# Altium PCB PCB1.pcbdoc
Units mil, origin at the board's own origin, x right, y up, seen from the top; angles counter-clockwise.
Board outline 4705 x 4455 mil, 2 copper layers (Top Layer, Bottom Layer), stack 62.206 mil thick; 55 components, 35 nets, 221 pads, 60 vias.
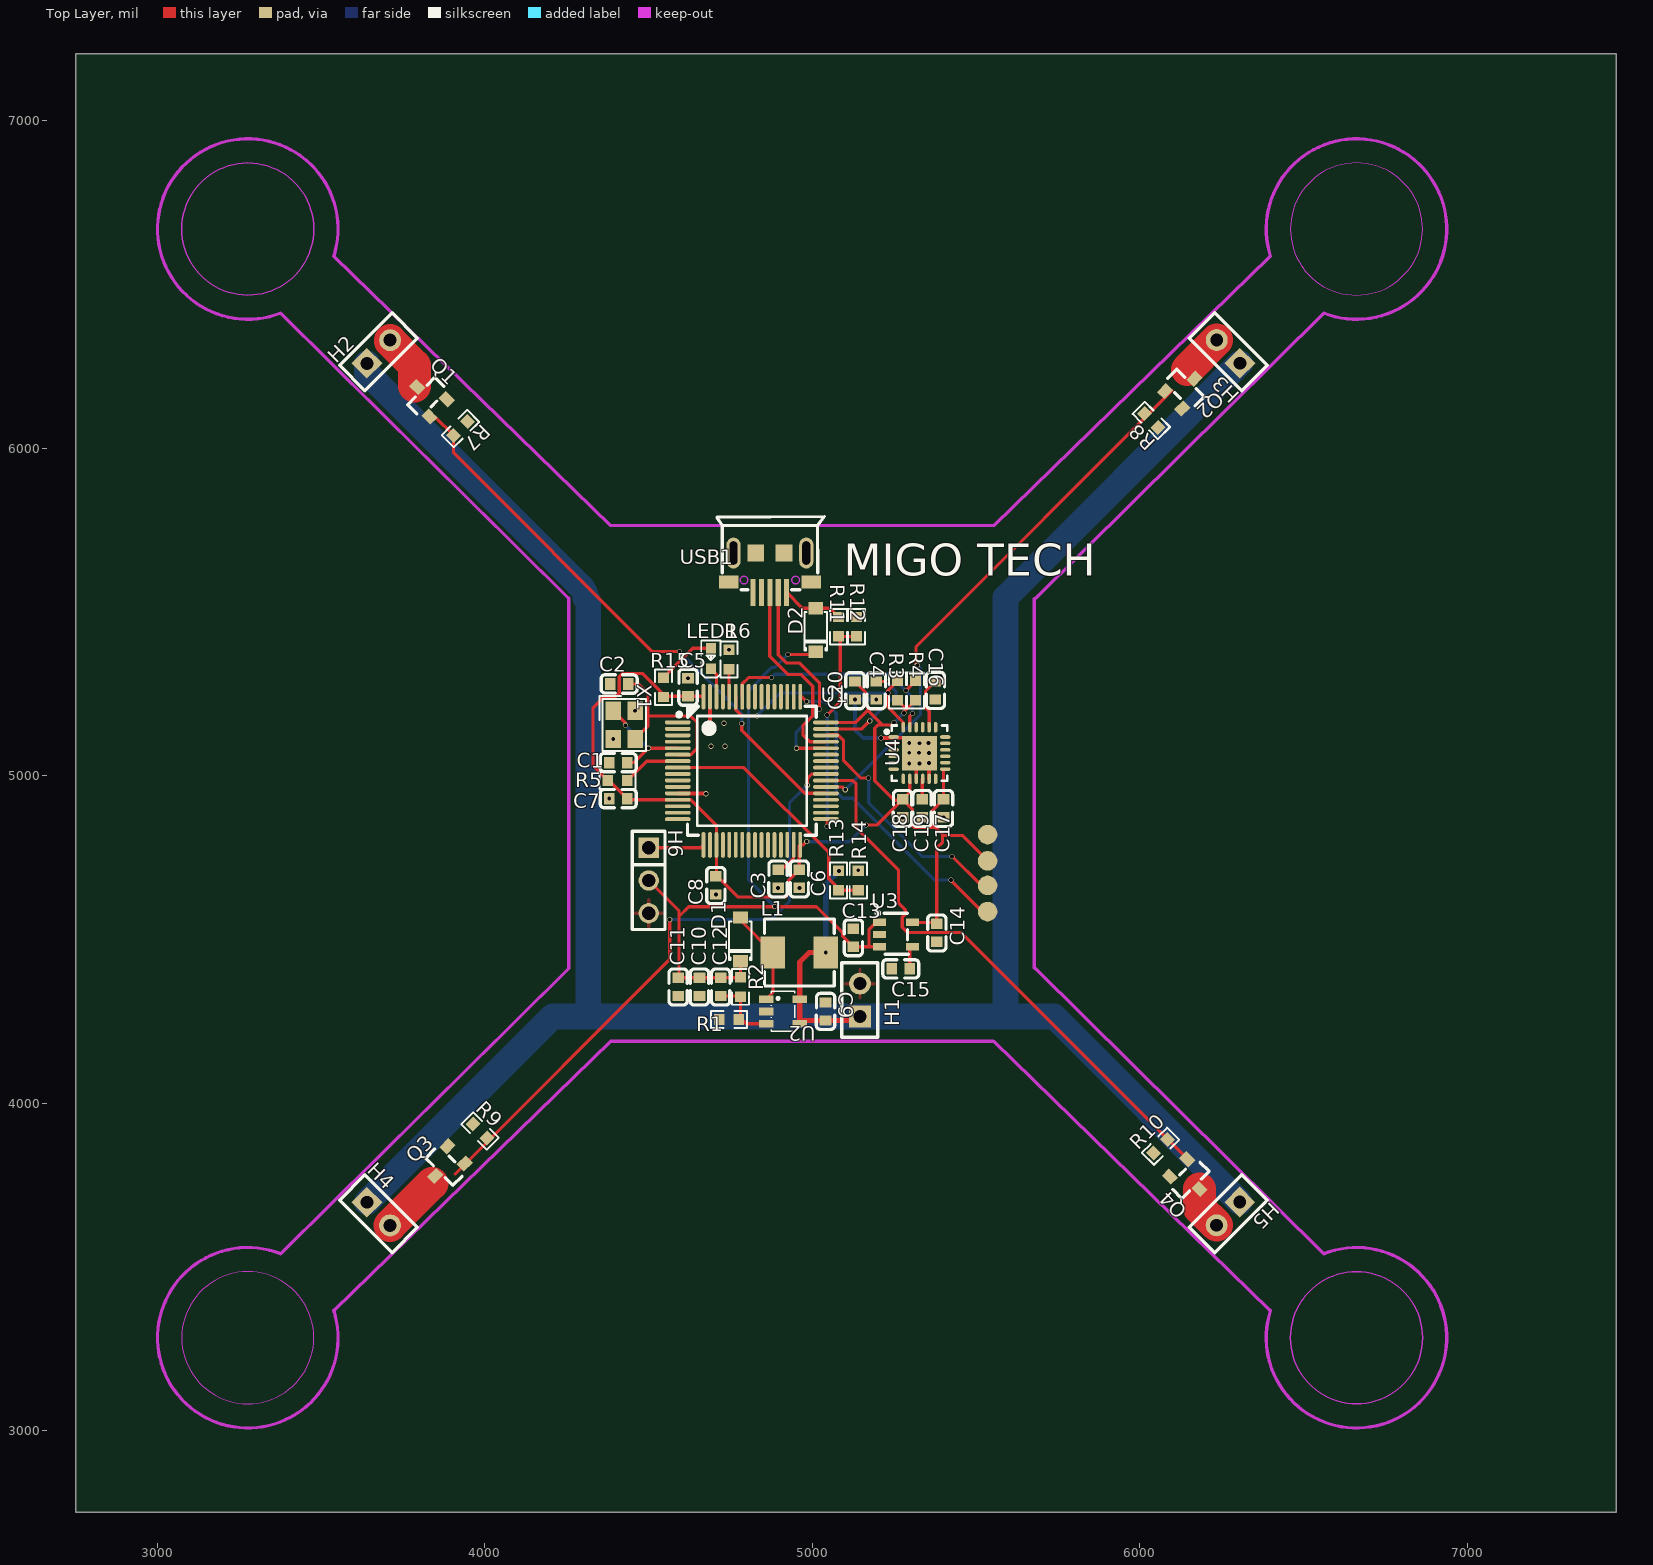
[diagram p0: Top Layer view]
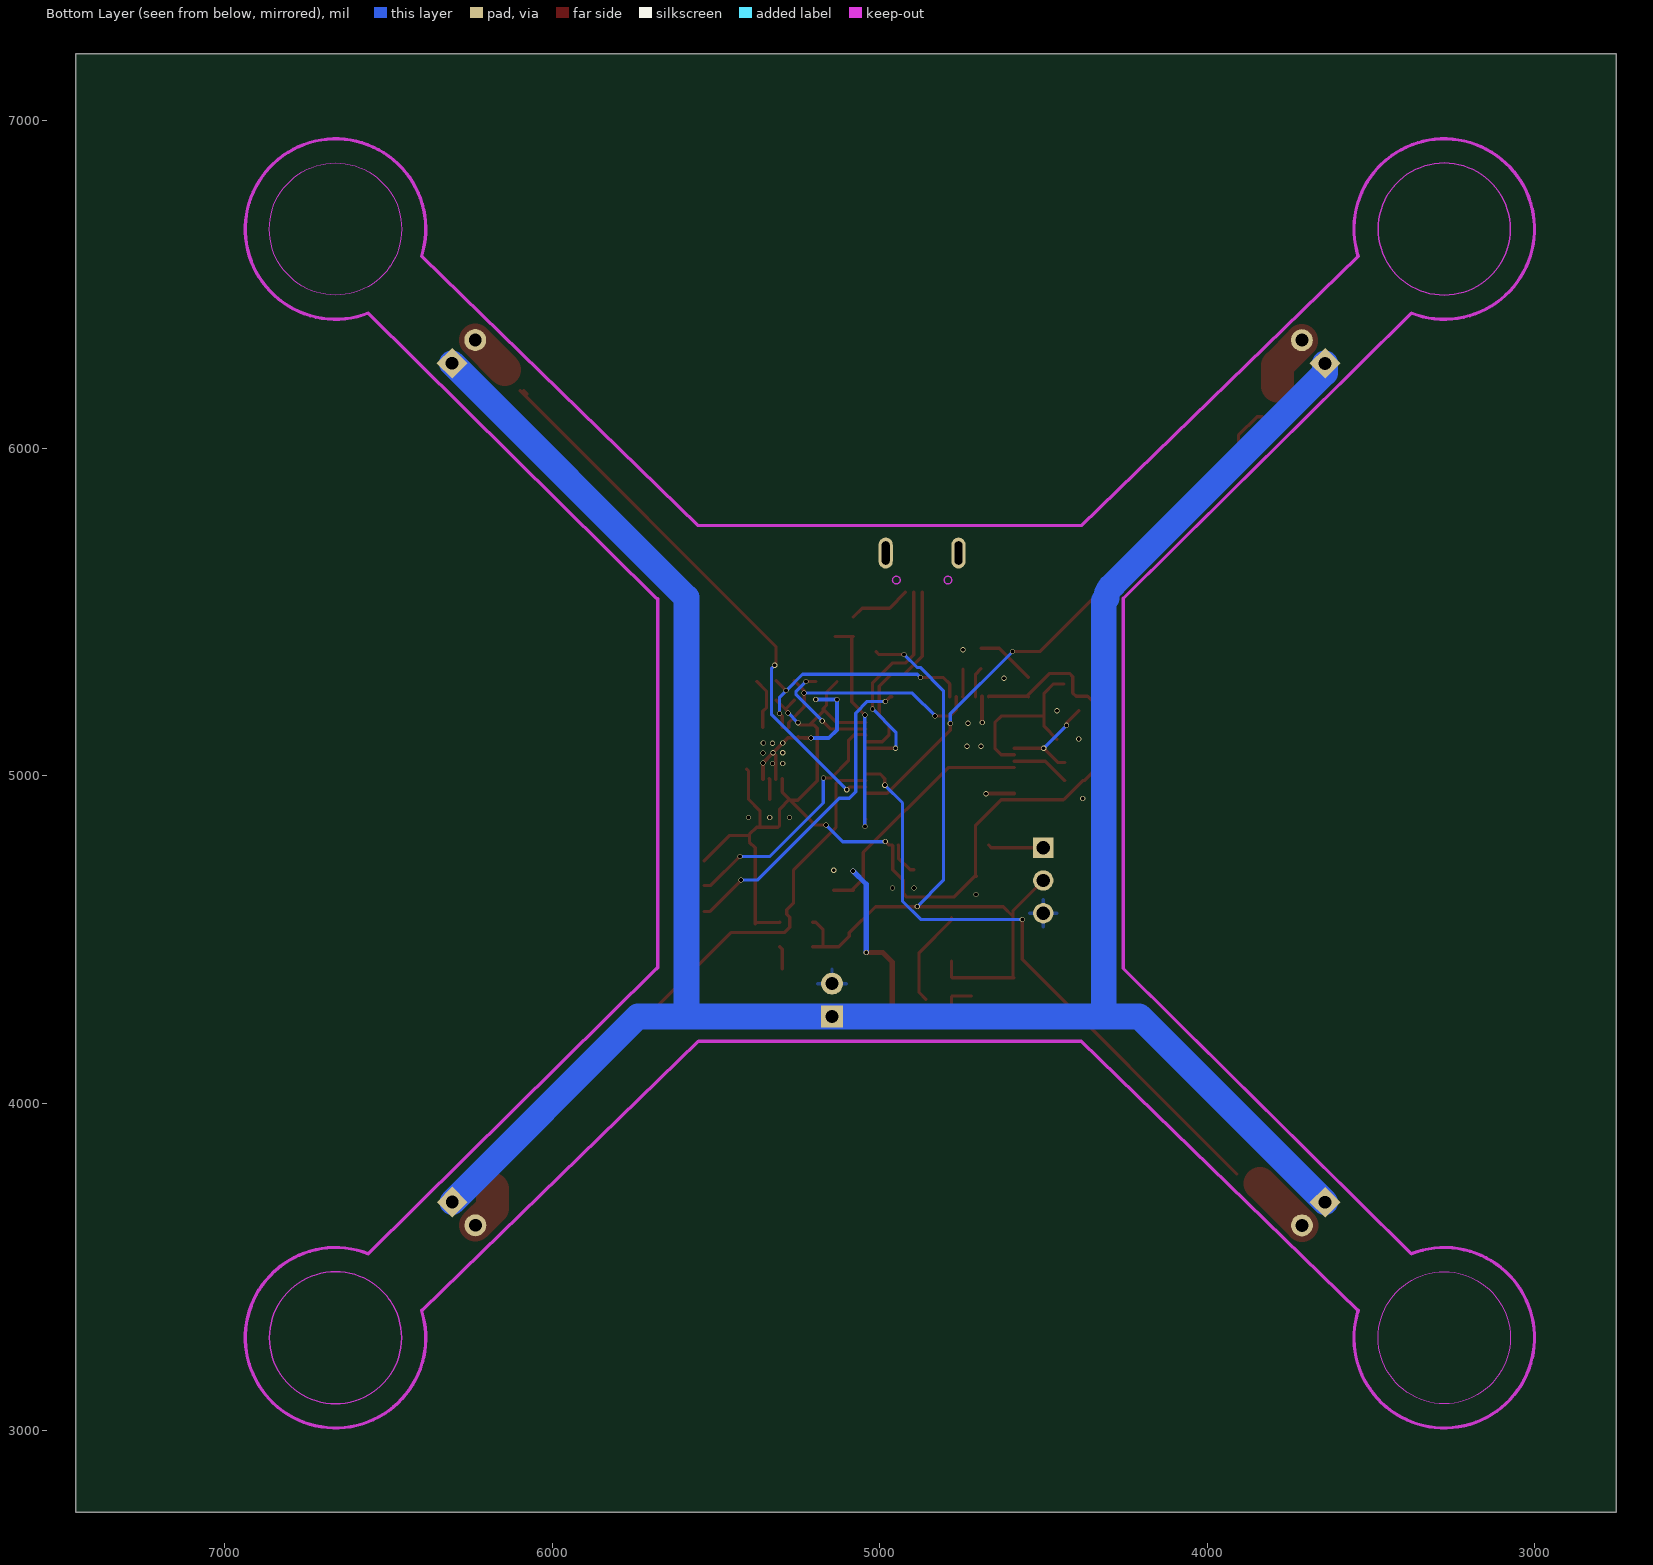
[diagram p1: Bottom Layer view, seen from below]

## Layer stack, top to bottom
Top Solder Mask Layer: solder mask 0.394, Dk 3.3
Top Layer: signal copper 1.379
Dielectric1: surface 59.449, FR4, Dk 4.5
Bottom Layer: signal copper 1.378
Bottom Solder Mask Layer: solder mask 0.394, Dk 3.3

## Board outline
7455,2750 2750,2750 2750,7205 7455,7205

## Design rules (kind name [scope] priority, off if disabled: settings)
BoardOutlineClearance copperThickness1oz [All] p0: genericclearance=10 ignorepadtopadclearanceinfootprint=FALSE except(0: Arc-SplitContinuation Track-SplitContinuation SMDPad-SplitContinuation THPad-SplitContinuation Via-SplitContinuation Fill-SplitContinuation Poly-SplitContinuation Region-SplitContinuation Text-SplitContinuation)
BoardOutlineClearance copperThickness2oz [All] p0: genericclearance=10 ignorepadtopadclearanceinfootprint=FALSE except(0: Arc-SplitContinuation Track-SplitContinuation SMDPad-SplitContinuation THPad-SplitContinuation Via-SplitContinuation Fill-SplitContinuation Poly-SplitContinuation Region-SplitContinuation Text-SplitContinuation)
BoardOutlineClearance Plane_innerPlane [All] p0: genericclearance=10 ignorepadtopadclearanceinfootprint=FALSE except(0: Arc-SplitContinuation Track-SplitContinuation SMDPad-SplitContinuation THPad-SplitContinuation Via-SplitContinuation Fill-SplitContinuation Poly-SplitContinuation Region-SplitContinuation Text-SplitContinuation)
BoardOutlineClearance Copper_copperRegion [All] p0: genericclearance=10 ignorepadtopadclearanceinfootprint=FALSE except(0: Arc-SplitContinuation Track-SplitContinuation SMDPad-SplitContinuation THPad-SplitContinuation Via-SplitContinuation Fill-SplitContinuation Poly-SplitContinuation Region-SplitContinuation Text-SplitContinuation)
BoardOutlineClearance otherClearance [All] p0: genericclearance=10 ignorepadtopadclearanceinfootprint=FALSE except(0: Arc-SplitContinuation Track-SplitContinuation SMDPad-SplitContinuation THPad-SplitContinuation Via-SplitContinuation Fill-SplitContinuation Poly-SplitContinuation Region-SplitContinuation Text-SplitContinuation)
Clearance copperThickness1oz [All] p1: gap=7 ignorepadtopadclearanceinfootprint=FALSE
Clearance copperThickness2oz [All] p1: gap=7 ignorepadtopadclearanceinfootprint=FALSE
Clearance Plane_innerPlane [All] p1: gap=7 ignorepadtopadclearanceinfootprint=FALSE
Clearance Copper_copperRegion [All] p1: gap=7 ignorepadtopadclearanceinfootprint=FALSE
Clearance otherClearance [All] p1: gap=7 ignorepadtopadclearanceinfootprint=FALSE
DiffPairsRouting differentialPair [All] p1: maxuncoupledlength=10 minlimit=5.9843 maxlimit=Infinity mostfreqgap=5.9843 toplayer_minwidth=5 toplayer_prefwidth=10 toplayer_maxwidth=100 bottomlayer_minwidth=5 bottomlayer_prefwidth=10 bottomlayer_maxwidth=100
PasteMaskExpansion pasteMaskExpansion [All] p1: expansion=0
PlaneConnect innerPlane [All] p1: planeconnectstyle=Relief reliefexpansion=20 reliefentries=4 reliefconductorwidth=10 reliefairgap=10
PolygonConnect copperRegion [All] p1: connectstyle=Relief reliefentries=4 reliefconductorwidth=10 polygonreliefangle="90 Angle" airgapwidth=10
RoutingVias viaSize [All] p1: viastyle="Through Hole" holewidth=12.0078 minholewidth=11.811 maxholewidth=248.0314 width=12.0078 minwidth=11.811 maxwidth=248.0314
SolderMaskExpansion solderMaskExpansion [All] p1: useseparateexpansions=TRUE expansion=2.0079 expansionbottom=2.0079
Width copperThickness1oz [All] p1: maxlimit=100 minlimit=5 preferedwidth=10
Width copperThickness2oz [All] p1: maxlimit=118 minlimit=8 preferedwidth=10

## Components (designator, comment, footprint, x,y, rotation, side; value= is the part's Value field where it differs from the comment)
C1 "" C0603 4407.25,5040 r0 top
C2 "" C0603 4410,5280 r0 top
C3 "" C0603 4895,4685 r90 top
C4 "" C0603 5195,5260 r90 top
C5 "" C0603 4620,5270 r270 top
C6 "" C0603 4960,4685 r90 top
C7 "" C0603 4407.25,4930 r0 top
C8 "" C0603 4705,4665 r90 top
C9 "" C0603 5040,4280 r270 top
C10 "" C0603 4655,4355 r90 top
C11 "" C0603 4590,4355 r90 top
C12 "" C0603 4720,4355 r90 top
C13 "" C0603 5125,4505 r270 top
C14 "" C0603 5380,4520 r90 top
C15 "" C0603 5270,4410 r0 top
C16 "" C0603 5375.26,5260.26 r270 top
C17 "" C0603 5400.26,4900.26 r90 top
C18 "" C0603 5275.26,4900.26 r90 top
C19 "" C0603 5335.26,4900.26 r90 top
C20 "" C0603 5130,5260 r90 top
D1 "" SOD-123_L2.8-W1.8-LS3.7-RD 4780,4500 r90 top
D2 "" SOD-123_L2.8-W1.8-LS3.7-RD 5010,5445 r90 top
H1 "" HDR-TH_2P-P2.54-V-F 5145,4315 r90 top
H2 "" HDR-TH_2P-P2.54-V-F 3675,6294.72 r45 top
H3 "" HDR-TH_2P-P2.54-V-F 6270,6295 r135 top
H4 "" HDR-TH_2P-P2.54-V-F 3674.72,3662.07 r315 top
H5 "" HDR-TH_2P-P2.54-V-F 6269.72,3662.35 r225 top
H6 "" HDR-TH_3P-P2.54-V-F 4500,4680 r270 top
L1 "" IND-SMD_L5.4-W5.2_FXL0530 4960,4460 r0 top
LED1 "" LED_0603 4690,5360 r90 top
Q1 "" SOT-23_L2.9-W1.3-P1.90-LS2.4-BR 3825,6155 r315 top
Q2 "" SOT-23_L2.9-W1.3-P1.90-LS2.4-BR 6135,6180 r225 top
Q3 "" SOT-23_L2.9-W1.3-P1.90-LS2.4-BR 3880,3810 r45 top
Q4 "" SOT-23_L2.9-W1.3-P1.90-LS2.4-BR 6150,3770 r135 top
R1 "" R0603 4745,4255 r0 top
R2 "" R0603 4780,4355 r90 top
R3 "" R0603 5260.26,5260.26 r270 top
R4 "" R0603 5315.26,5260.26 r270 top
R5 "" R0603 4404.45,4985 r0 top
R6 "" R0603 4745,5355 r270 top
R7 "" R0603 3925,6060 r225 top
R8 "" R0603 6035,6085 r135 top
R9 "" R0603 3985,3915 r315 top
R10 "" R0603 6063.25,3868.51 r45 top
R11 "" R0603 5080,5455 r270 top
R12 "" R0603 5135,5455 r90 top
R13 "" R0603 5080,4680 r90 top
R14 "" R0603 5140,4680 r270 top
R15 "" R0603 4545,5270 r270 top
U1 "" LQFP-64_L10.0-W10.0-P0.50-LS12.0-BL 4815,5015 r270 top
U2 "" SOT-23-5_L3.0-W1.7-P0.95-LS2.8-BR 4910,4280 r180 top
U3 "" SOT-23-5_L3.0-W1.7-P0.95-LS2.8-TL 5255,4515 r0 top
U4 "" QFN-24_L4.0-W4.0-P0.50-BL-EP2.7 5326.89,5069.14 r270 top
USB1 "" MICRO-USB-SMD_5P-P0.65-H-F_MICRO5.9MMUSB 4870,5620 r180 top
X1 "" CRYSTAL-SMD_4P-L3.2-W2.5-BL 4425,5155 r270 top

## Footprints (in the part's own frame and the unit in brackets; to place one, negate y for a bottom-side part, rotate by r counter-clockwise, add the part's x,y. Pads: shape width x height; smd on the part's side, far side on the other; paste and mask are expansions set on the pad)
C0603 [mm]
  rect 0.8x0.9 smd: 1(-0.7,0) 2(0.7,0)
  silkscreen extent -1.41,-0.71 1.39,0.72
CRYSTAL-SMD_4P-L3.2-W2.5-BL [mm]
  rect 1.4x1.2 smd: 1(-1.1,-0.85) 2(1.1,-0.85) 3(1.1,0.85) 4(-1.1,0.85)
  silkscreen extent -2.26,-1.91 2.03,1.68
HDR-TH_2P-P2.54-V-F [mm]
  rect 1.7x1.7 hole 1: 1(-1.27,0)
  round 1.7 hole 1: 2(1.27,0)
  silkscreen extent -2.88,-1.39 2.88,1.4
HDR-TH_3P-P2.54-V-F [mil]
  rect 62x62 hole 40.16: 1(-100,0)
  round 62 hole 40.16: 2(0,0) 3(100,0)
  silkscreen extent -150,-50 150,50
IND-SMD_L5.4-W5.2_FXL0530 [mm]
  rect 1.9x2.5 smd: 1(-2.05,0) 2(2.05,0)
  silkscreen extent -2.7,-2.6 2.7,2.6
LED_0603 [mil]
  rect 31.5x31.5 smd: 1(-33.5,-0.4) 2(29.5,-0.2)
  silkscreen extent -61,-30 53,30
LQFP-64_L10.0-W10.0-P0.50-LS12.0-BL [mm]
  oval 0.3x2 smd: 1(-3.75,-5.75) 2(-3.25,-5.75) 3(-2.75,-5.75) 4(-2.25,-5.75) 5(-1.75,-5.75) 6(-1.25,-5.75) 7(-0.75,-5.75) 8(-0.25,-5.75) 9(0.25,-5.75) 10(0.75,-5.75) 11(1.25,-5.75) 12(1.75,-5.75) 13(2.25,-5.75) 14(2.75,-5.75) 15(3.25,-5.75) 16(3.75,-5.75) 33(3.75,5.75) 34(3.25,5.75) 35(2.75,5.75) 36(2.25,5.75) 37(1.75,5.75) 38(1.25,5.75) 39(0.75,5.75) 40(0.25,5.75) 41(-0.25,5.75) 42(-0.75,5.75) 43(-1.25,5.75) 44(-1.75,5.75) 45(-2.25,5.75) 46(-2.75,5.75) 47(-3.25,5.75) 48(-3.75,5.75)
  oval 2x0.3 smd: 17(5.75,-3.75) 18(5.75,-3.25) 19(5.75,-2.75) 20(5.75,-2.25) 21(5.75,-1.75) 22(5.75,-1.25) 23(5.75,-0.75) 24(5.75,-0.25) 25(5.75,0.25) 26(5.75,0.75) 27(5.75,1.25) 28(5.75,1.75) 29(5.75,2.25) 30(5.75,2.75) 31(5.75,3.25) 32(5.75,3.75) 49(-5.75,3.75) 50(-5.75,3.25) 51(-5.75,2.75) 52(-5.75,2.25) 53(-5.75,1.75) 54(-5.75,1.25) 55(-5.75,0.75) 56(-5.75,0.25) 57(-5.75,-0.25) 58(-5.75,-0.75) 59(-5.75,-1.25) 60(-5.75,-1.75) 61(-5.75,-2.25) 62(-5.75,-2.75) 63(-5.75,-3.25) 64(-5.75,-3.75)
  silkscreen extent -5,-5.79 5,5
MICRO-USB-SMD_5P-P0.65-H-F_MICRO5.9MMUSB [mm]
  rect 0.4x2.1 smd: 1(-1.3,1.525) 2(-0.65,1.525) 3(0,1.525) 4(0.65,1.525) 5(1.3,1.525)
  rect 1.5x1 smd: 6(-3.2,0.725) 6(3.2,0.725)
  oval 1.1x2.4 hole 0.6 slot 1.8 at 90 deg: 6(-2.825,-1.525) 6(2.825,-1.525)
  rect 1.3x1.3 smd: 6(-1.1,-1.525) 6(1.1,-1.525)
  Board Outline Layer circle w0.003: c2,0.575 r0.3
  Board Outline Layer circle w0.003: c-2,0.575 r0.3
  Board Outline Layer region: 1.7,0.575 1.73,0.705 1.813,0.81 1.933,0.868 2.067,0.868 2.187,0.81 2.27,0.705 2.3,0.575 2.3,0.575 2.27,0.445 2.187,0.341 2.067,0.283 1.933,0.283 1.813,0.341 1.73,0.445 1.7,0.575
  Board Outline Layer region: 1.7,0.575 1.73,0.705 1.813,0.81 1.933,0.868 2.067,0.868 2.187,0.81 2.27,0.705 2.3,0.575 2.3,0.575 2.27,0.445 2.187,0.341 2.067,0.283 1.933,0.283 1.813,0.341 1.73,0.445 1.7,0.575
  Board Outline Layer region: -2.3,0.575 -2.27,0.705 -2.187,0.81 -2.067,0.868 -1.933,0.868 -1.813,0.81 -1.73,0.705 -1.7,0.575 -1.7,0.575 -1.73,0.445 -1.813,0.341 -1.933,0.283 -2.067,0.283 -2.187,0.341 -2.27,0.445 -2.3,0.575
  Board Outline Layer region: -2.3,0.575 -2.27,0.705 -2.187,0.81 -2.067,0.868 -1.933,0.868 -1.813,0.81 -1.73,0.705 -1.7,0.575 -1.7,0.575 -1.73,0.445 -1.813,0.341 -1.933,0.283 -2.067,0.283 -2.187,0.341 -2.27,0.445 -2.3,0.575
  silkscreen extent -4.23,-4.35 4.09,1.32
QFN-24_L4.0-W4.0-P0.50-BL-EP2.7 [mm]
  oval 0.28x0.8 smd: 1(-1.25,-2) 2(-0.75,-2) 3(-0.25,-2) 4(0.25,-2) 5(0.75,-2) 6(1.25,-2) 13(1.25,2) 14(0.75,2) 15(0.25,2) 16(-0.25,2) 17(-0.75,2) 18(-1.242,2)
  oval 0.8x0.28 smd: 7(2,-1.25) 8(2,-0.75) 9(2,-0.25) 10(2,0.25) 11(2,0.75) 12(2,1.25) 19(-2,1.25) 20(-2,0.75) 21(-2,0.25) 22(-2,-0.25) 23(-2,-0.75) 24(-2,-1.25)
  rect 2.7x2.7 smd: 25(0.012,0)
  silkscreen extent -2.14,-2.79 2.16,2.15
R0603 [mil]
  rect 31.75x34.02 smd: 1(-29.66,0) 2(29.66,0)
  silkscreen extent -55,-26 55,26
SOD-123_L2.8-W1.8-LS3.7-RD [mm]
  rect 0.95x1.15 smd: 1(-1.692,0) 2(1.692,0)
  silkscreen extent -1.58,-0.87 1.41,0.87
SOT-23-5_L3.0-W1.7-P0.95-LS2.8-BR [mm]
  rect 1.1x0.6 smd: 1(1.3,-0.95) 2(1.3,0) 3(1.3,0.95) 4(-1.3,0.95) 5(-1.3,-0.95)
  silkscreen extent -0.9,-1.55 0.9,1.55
SOT-23-5_L3.0-W1.7-P0.95-LS2.8-TL [mm]
  rect 1x0.55 smd: 1(-1.271,0.95) 2(-1.271,0) 3(-1.271,-0.95) 4(1.271,-0.95) 5(1.271,0.95)
  silkscreen extent -1.52,-1.52 0.97,1.78
SOT-23_L2.9-W1.3-P1.90-LS2.4-BR [mm]
  rect 1x0.8 smd: 1(1.15,-0.95) 2(1.15,0.95) 3(-1.15,0)
  silkscreen extent -0.7,-1.5 0.7,1.5

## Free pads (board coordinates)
  round 60 smd: 1(5535,4585) 1(5535,4665) 1(5535,4740) 1(5535,4820)

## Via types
v1: diameter 15.75, hole 12.01, Top Layer to Bottom Layer, 31 vias
v2: diameter 15.75, hole 11.81, Top Layer to Bottom Layer, 29 vias

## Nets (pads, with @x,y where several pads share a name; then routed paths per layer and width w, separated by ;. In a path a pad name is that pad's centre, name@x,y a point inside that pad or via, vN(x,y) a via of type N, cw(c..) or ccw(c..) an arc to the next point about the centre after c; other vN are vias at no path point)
3.3V: C5.2 C6.2 C7.2 C8.2 C14.2 C17.2 C18.2 C20.2 pad.1@5535,4740 R3.2 R4.2 R5.1 R15.2 U1.13 U1.19 U1.32 U1.48 U1.64 U3.5 U4.8 U4.13 | length 3798.3
  Top Layer w9.92: 5214.58,5154.65 5199.65,5154.65 5190.55,5145.55 5190.55,4984.45 5250,4925 C18.2@5272.44,4925 ; 5224.65,5154.65 5242.09,5154.65 v1(5249.29,5161.85) ; v1(5279.29,5191.85) 5279.29,5194.63 5289.81,5205.15 R4.2 ; U4.8 5297.36,4949.92 C18.2 5305.26,4897.82 5305.26,4847.82 5310.26,4842.82 5375.14,4842.82 5375.14,4842.93 ; C17.2 5400.26,5014.56 U4.13
  Top Layer w10: R15.2 4547.1,5242.44 R15.2@4550,5242.44 ; U1.64 4666.29,5242.44 C5.2 R15.2@4550,5242.44 ; C8.2 4706.73,4694.29 C8.2@4706.73,4696.13 ; v1(4982.64,4798.63) 4972.64,4788.63 U1.32 4960,4785.99 C6.2 4926.73,4679.29 4926.73,4639.29 4916.73,4629.29 4773.57,4629.29 C8.2@4706.73,4696.13 ; U1.48 5132.64,5162.64 5172.59,5202.59 ; C20.2 5162.09,5255.47 5162.09,5214.65 5172.59,5204.15 5172.59,5202.59 ; v1(5163.18,4849.17) 5196.61,4849.17 5272.44,4925 C18.2 ; 5224.65,5154.65 5214.58,5154.65 5172.59,5196.64 5172.59,5202.59 ; R3.2 5285.7,5205.15 5289.81,5205.15 ; U3.5 5305.61,4551.85 C14.2@5380,4551.85 ; C14.2 C14.2@5380,4551.85 ; C17.2 5365.26,4892.82 5365.26,4844.74 5367.07,4842.93 5375.14,4842.93 5397.46,4820.61 5397.46,4817.46 ; pad.1@5535,4740 5457.54,4817.46 5397.46,4817.46 ; R15.2@4550,5242.44 4480,5312.44 4420,5312.44 4410,5302.44 4410,5252.44 4400,5242.44 4364.79,5242.44 4330,5207.65 4330,5029.79 R5.1 4379.81,4985 C7.2 4438.39,4926.42 U1.13 4628.63,4926.42 4706.73,4848.32 U1.19 C8.2@4706.73,4696.13 ; C14.2@5380,4551.85 5380,4780 5397.46,4797.46 5397.46,4817.46
  Bottom Layer w9.92: v1(5249.29,5161.85) v1(5279.29,5191.85)
  Bottom Layer w10: v1(4982.64,4798.63) 5112.64,4798.63 v1(5163.18,4849.17)
5V: C10.2 C11.2 C12.2 C13.2 D1.1 D2.1 H6.2 R2.2 U3.1 U3.3 | length 2298.1
  Top Layer w10: H6.2 4592.5,4587.5 4592.5,4570.06 ; C11.2 C11.2@4592.5,4382.56 ; D1.1 R2.2 4777.9,4382.56 C12.2 C10.2 C11.2@4592.5,4382.56 ; v1(4925,5370.06) 5001.69,5370.06 D2.1 ; U3.3@5204.79,4477.44 5172.5,4477.44 ; U3.1 5194.95,4552.4 5172.5,4529.96 5172.5,4477.44 ; C11.2@4592.5,4382.56 4592.5,4570.06 ; 4592.5,4570.06 4622.5,4600.06 v1(4885,4600.06) 5012.38,4600.06 5092.38,4520.06 5092.38,4510.06 C13.2 5172.5,4477.44
  Bottom Layer w10: v1(4885,4600.06) 4805,4680.06 4805,5260.06 4875.71,5330.77 4885.71,5330.77 v1(4925,5370.06)
$1N1934: C12.1 R1.2 R2.1 U2.3 | length 219.6
  Top Layer w10: C12.1 4777.9,4327.44 R2.1 R1.2@4780,4260.34 ; R1.2 R1.2@4780,4260.34 ; U2.3 4797.74,4242.6 R1.2@4780,4260.34
$1N1998: D1.2 L1.1 U2.1 | length 298.8
  Top Layer w10: D1.2 4780,4559.29 L1.1 4879.29,4337.88 U2.1
$1N2482: C15.2 U3.4 | length 70.7
  Top Layer w10: C15.2 5297.56,4470.1 U3.4
$1N2921: C16.1 U4.20 | length 157
  Top Layer w9.92: U4.20 5356.42,5196.66 5345.26,5207.82 5345.26,5257.82 C16.1
$1N3157: C19.2 U4.10 | length 63.2
  Top Layer w9.92: C19.2 5335.26,4988.93 U4.10
$1N3541: H2.2 Q1.3 | length 171
  Top Layer w100: H2.2 3710.36,6327.23 3785,6252.59 Q1.3@3785,6190
$1N3659: H3.2 Q2.3 | length 127.8
  Top Layer w100: 6144.29,6240 H3.2
$1N3775: H4.2 Q3.3 | length 181.4
  Top Layer w100: H4.2 3838.36,3755
$1N3891: H5.2 Q4.3 | length 132.7
  Top Layer w100: Q4.3 6182.01,3679.35 H5.2
$1N4179: D2.2 R11.1 USB1.1 | length 190
  Top Layer w10: USB1.1 4969.51,5511.63 D2.2 5053.03,5511.63 R11.1
$1N4669: LED1.2 R15.1 | length 182.4
  Top Layer w10: R15.1 4634.84,5389.5 LED1.2
BAT_DET: R13.1 R14.2 U1.8 | length 758.4
  Top Layer w10: U1.8 4790.5,5024.84 5049.64,4765.7 5049.64,4685.7 R13.1@5085,4650.34 ; R13.1 R13.1@5085,4650.34 ; R14.2 R13.1@5085,4650.34
BOOT0: R6.2 U1.60 | length 84.4
  Top Layer w10: R6.2 4745,5242.47 U1.60
GND: C1.1 C2.1 C3.1 C4.1 C5.1 C6.1 C7.1 C8.1 C9.1 C10.1 C11.1 C13.1 C14.1 C15.1 C16.2 C17.1 C18.1 C19.1 C20.1 H1.2 H6.3 pad.1@5535,4820 Q1.2 Q2.2 Q3.2 Q4.2 R1.1 R6.1 R7.1 R8.1 R9.1 R10.1 R12.2 R14.1 U1.12 U1.63 U2.2 U3.2 U4.1 U4.9 U4.11 U4.18 U4.25 USB1.5 X1.2 X1.4 | length 726.2
  Top Layer w11.81: U1.12 4673.9,4946.1 v2(4675,4945) ; v2(4686.3,5162.32) 4687.05,5163.08 U1.63 ; v2(5209.43,5115) 5229.64,5115 5230.71,5116.07 5245.87,5116.07 U4.1 5250.43,5116.07 5279.47,5116.07 v2(5295.77,5099.77) U4.25 v2(5356.42,5039.12) U4.11 ; U4.9 5317.05,5062.05 v2(5325,5070)
  Bottom Layer w11.81: v2(5195,5232.44) v2(5130,5232.44) 5130,5140 5155,5115 v2(5209.43,5115)
  other v2: 4705,4637.44 4895,4657.44 4960,4657.44 5140,4711.3 5275.26,4872.7 5335.26,4872.7 5400.26,4872.7 4379.69,4930 5295.77,5037.58 5326.89,5037.58 5356.42,5069.14 5295.77,5070.25 4690,5090 4733.09,5090 5326.89,5099.11 5355,5100 4391.54,5111.69 4730,5160 4458.47,5198.31 4620,5297.56 4745,5384.66
IIC_SCL: R4.1 U1.58 U4.23 | length 737.6
  Top Layer w9.92: U1.58 4785.47,5280.13 4805.26,5299.92 v1(4875.26,5299.92) ; v1(5285.26,5259.92) R4.1 ; U4.23 5297.36,5182.02 v1(5305.26,5189.92)
  Bottom Layer w9.92: v1(4875.26,5299.92) 4885.26,5309.92 5235.26,5309.92 v1(5285.26,5259.92) 5305.26,5239.92 v1(5305.26,5189.92)
IIC_SDA: R3.1 U1.59 U4.24 | length 715.4
  Top Layer w9.92: R3.1 5230.26,5259.92 5230.26,5209.92 5277.68,5162.5 U4.24
  Top Layer w10: U1.59 4765.79,5201.37 4784.68,5182.48 v1(4830.26,5182.48)
  Bottom Layer w10: v1(4830.26,5182.48) 4900.26,5252.48 v1(5230.26,5252.48)
LED0: LED1.1 U1.62 | length 91.9
  Top Layer w10: LED1.1 4706.73,5310.17 U1.62
NRST: R5.2 U1.7 | length 179.2
  Top Layer w10: R5.2 4493.64,5044.53 U1.7
PPM: H6.1 U1.17 | length 170.9
  Top Layer w10: H6.1 4658.73,4780 U1.17
PWM1: Q1.1 R7.2 U1.37 | length 1747.7
  Top Layer w10: Q1.1 3846.52,6096.54 R7.2 3904.03,5985.97 4510.97,5379.03 v1(4594.03,5379.03) ; v1(4784.03,5159.03) 4784.03,5139.03 4976.95,4946.1 U1.37
  Bottom Layer w10: v1(4594.03,5379.03) 4784.03,5189.03 v1(4784.03,5159.03)
PWM2: Q2.1 R8.2 U1.38 | length 1720.5
  Top Layer w10: U1.38 5091.7,4965.79 v1(5100.27,4957.22) ; v1(5320.27,5337.22) 5316.22,5341.27 5316.22,5394.18 Q2.1@6097.49,6175.45 ; Q2.1@6076.54,6164.43 6076.54,6165.44 Q2.1@6086.54,6175.45
  Bottom Layer w10: v1(5100.27,4957.22) 5330.27,5187.22 5330.27,5327.22 v1(5320.27,5337.22)
PWM3: Q4.1 R10.2 U1.39 | length 1764.9
  Top Layer w10: U1.39 5041.84,4985 5123.24,4985 5133.24,4975 5133.24,4841.57 5262.53,4712.28 5262.53,4612.28 5283.53,4591.28 5283.53,4576.92 5274.39,4567.78 5274.39,4537.03 5290.59,4520.83 5453.98,4520.83 6144.43,3830.38 Q4.1
PWM4: Q3.1 R9.2 U1.40 | length 1897.8
  Top Layer w10: 3908.46,3783.46 4564.03,4439.03 v1(4564.03,4560.97) ; v1(4984.03,4970.97) 4984.03,4990.97 4998.21,5005.16 U1.40
  Bottom Layer w10: v1(4564.03,4560.97) 4874.03,4560.97 4930,4616.95 4930,4916.95 v1(4984.03,4970.97)
SWCLK: pad.1@5535,4585 U1.49 | length 985.1
  Top Layer w10: U1.49 4967.51,5241.37 v1(4982.51,5226.37) ; v1(5422.64,4681.37) 5519.01,4585 pad.1@5535,4585
  Bottom Layer w10: v1(4982.51,5226.37) 4982.87,5226.73 5037.28,5226.73 5072.64,5191.37 5072.64,4951.37 5092.64,4931.37 5123.63,4931.37 5373.63,4681.37 v1(5422.64,4681.37)
SWDIO: pad.1@5535,4665 U1.46 | length 767.1
  Top Layer w10: U1.46 5044.16,5126.06 5076.24,5126.06 5095,5107.3 5095,5045 5146.73,4993.27 v1(5171.73,4993.27) ; v1(5426.73,4753.27) 5515,4665 pad.1@5535,4665
  Bottom Layer w10: v1(5171.73,4993.27) 5171.73,4916.66 5335.12,4753.27 v1(5426.73,4753.27)
USB_D+: U1.45 USB1.3 | length 604.9
  Top Layer w10: USB1.3 4870,5364.95 4926.01,5308.94 4966.01,5308.94 5001.37,5273.58 5001.37,5183.58 4971.37,5153.58 4971.37,5123.58 4991.37,5103.58 U1.45
USB_D-: U1.44 USB1.2 | length 671.7
  Top Layer w10: USB1.2 4895.59,5369.68 4921.37,5343.9 4961.37,5343.9 5021.37,5283.9 v1(5021.37,5203.9) ; v1(4951.37,5083.9) U1.44
  Bottom Layer w10: v1(4951.37,5083.9) 4950,5085.27 4950,5132.53 v1(5021.37,5203.9)
USB_DETECT: R11.2 R12.1 U1.33 | length 675.1
  Top Layer w10: U1.33 5045,4863.73 v1(5045,4845.34) ; v1(5045,5185.34) 5085,5225.34 R11.2@5085,5425.34 ; R11.2 R11.2@5085,5425.34 ; R12.1 R11.2@5085,5425.34
  Bottom Layer w10: v1(5045,4845.34) v1(5045,5185.34)
VBAT: C9.2 H1.1 H2.1 H3.1 H4.1 H5.1 L1.2 R13.2 U2.4 U2.5 | length 8413
  Top Layer w15.75: v1(5040.71,4460) 4990,4460 4961.19,4431.19 U2.5 U2.4 4971.03,4252.44 C9.2 5132.44,4252.44 H1.1
  Bottom Layer w15.75: v1(5040.71,4460) 5040.71,4668.79 v1(5081.02,4709.1)
  Bottom Layer w78.74: H4.1 4206.94,4265 H1.1 5737.78,4265 H5.1 ; H2.1 3639.65,6230.18 4285.6,5584.22 cw(c4255.96,5542.5) 4307.14,5542.5 4315.28,5534.36 4315.28,4280 ; 5590,4275 5590,5544.29 H3.1
VCAP_1: C3.2 U1.31 | length 102.9
  Top Layer w10: C3.2 4906.88,4712.56 4942.24,4747.92 4942.24,4787.92 U1.31
VCAP_2: C4.2 U1.47 | length 339.4
  Top Layer w10: U1.47 5150.39,5142.95 v1(5175,5167.56) ; C4.2 v1(5225,5287.56)
  Bottom Layer w10: v1(5175,5167.56) 5255,5247.56 5255,5257.56 v1(5225,5287.56)
XIN: C1.2 U1.5 X1.1 | length 330.8
  Top Layer w10: X1.1 4428.71,5161.13 v1(4428.71,5153.9) ; C1.2 4454.81,5040 v1(4498.71,5083.9) U1.5
  Bottom Layer w10: v1(4428.71,5153.9) v1(4498.71,5083.9)
XOUT: C2.2 U1.6 X1.3 | length 532.8
  Top Layer w10: C2.2 4470,5280 4497.56,5252.44 4497.56,5182.5 ; X1.3 4497.56,5150.78 4497.56,5182.5 ; U1.6 4628.63,5064.21 4647.56,5083.14 4647.56,5162.5 4627.56,5182.5 4497.56,5182.5
pads on no net: U1.1 U1.2 U1.3 U1.4 U1.9 U1.10 U1.11 U1.14 U1.15 U1.16 U1.18 U1.20 U1.21 U1.22 U1.23 U1.24 U1.25 U1.26 U1.27 U1.28 U1.29 U1.30 U1.34 U1.35 U1.36 U1.41 U1.42 U1.43 U1.50 U1.51 U1.52 U1.53 U1.54 U1.55 U1.56 U1.57 U1.61 U4.2 U4.3 U4.4 U4.5 U4.6 U4.7 U4.12 U4.14 U4.15 U4.16 U4.17 U4.19 U4.21 U4.22 USB1.4 USB1.6

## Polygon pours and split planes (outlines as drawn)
GND on Top Layer (solid, remove dead copper, pour order 0): 3020,6930 7205,6930 7205,3000 3020,3000
GND on Bottom Layer (solid, remove dead copper, pour order 2): 3035,6955 6995,6955 6995,3020 3035,3020

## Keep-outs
Board Outline Layer:
  region: 3440.42,6552.89 cw(c3275.59,6669.41) 3275.59,6467.56 cw(c3275.59,6669.41) 3073.74,6669.41 cw(c3275.59,6669.41) 3275.59,6871.26 cw(c3275.59,6669.41) 3477.44,6669.41 cw(c3275.59,6669.41) 3442.62,6556.08 cw(c3438.49,6558.89) 3441.22,6554.7 cw(c3436.33,6555.78)
  region: 3440.42,6552.89 cw(c3275.59,6669.41) 3275.59,6467.56 cw(c3275.59,6669.41) 3073.74,6669.41 cw(c3275.59,6669.41) 3275.59,6871.26 cw(c3275.59,6669.41) 3477.44,6669.41 cw(c3275.59,6669.41) 3442.62,6556.08 cw(c3438.49,6558.89) 3441.22,6554.7 cw(c3436.33,6555.78)
  region: 6496.59,6552.89 ccw(c6661.42,6669.41) 6661.42,6467.56 ccw(c6661.42,6669.41) 6863.27,6669.41 ccw(c6661.42,6669.41) 6661.42,6871.26 ccw(c6661.42,6669.41) 6459.57,6669.41 ccw(c6661.42,6669.41) 6494.38,6556.08 ccw(c6498.52,6558.89) 6495.79,6554.7 ccw(c6500.67,6555.78)
  region: 6496.59,6552.89 ccw(c6661.42,6669.41) 6661.42,6467.56 ccw(c6661.42,6669.41) 6863.27,6669.41 ccw(c6661.42,6669.41) 6661.42,6871.26 ccw(c6661.42,6669.41) 6459.57,6669.41 ccw(c6661.42,6669.41) 6494.38,6556.08 ccw(c6498.52,6558.89) 6495.79,6554.7 ccw(c6500.67,6555.78)
  region: 3440.42,3400.1 ccw(c3275.59,3283.58) 3275.59,3485.43 ccw(c3275.59,3283.58) 3073.74,3283.58 ccw(c3275.59,3283.58) 3275.59,3081.73 ccw(c3275.59,3283.58) 3477.44,3283.58 ccw(c3275.59,3283.58) 3442.62,3396.91 ccw(c3438.49,3394.1) 3441.22,3398.29 ccw(c3436.33,3397.21)
  region: 3440.42,3400.1 ccw(c3275.59,3283.58) 3275.59,3485.43 ccw(c3275.59,3283.58) 3073.74,3283.58 ccw(c3275.59,3283.58) 3275.59,3081.73 ccw(c3275.59,3283.58) 3477.44,3283.58 ccw(c3275.59,3283.58) 3442.62,3396.91 ccw(c3438.49,3394.1) 3441.22,3398.29 ccw(c3436.33,3397.21)
  region: 6496.59,3400.1 cw(c6661.42,3283.58) 6661.42,3485.43 cw(c6661.42,3283.58) 6863.27,3283.58 cw(c6661.42,3283.58) 6661.42,3081.73 cw(c6661.42,3283.58) 6459.57,3283.58 cw(c6661.42,3283.58) 6494.38,3396.91 cw(c6498.52,3394.1) 6495.79,3398.29 cw(c6500.67,3397.21)
  region: 6496.59,3400.1 cw(c6661.42,3283.58) 6661.42,3485.43 cw(c6661.42,3283.58) 6863.27,3283.58 cw(c6661.42,3283.58) 6661.42,3081.73 cw(c6661.42,3283.58) 6459.57,3283.58 cw(c6661.42,3283.58) 6494.38,3396.91 cw(c6498.52,3394.1) 6495.79,3398.29 cw(c6500.67,3397.21)
  lines w0.1: 3073.74,3283.58 cw(c3275.59,3283.58) 3275.59,3485.43 cw(c3275.59,3283.58) 3440.42,3400.1 cw(c3436.33,3397.21) 3441.22,3398.29 cw(c3438.49,3394.1) 3442.62,3396.91 cw(c3275.59,3283.58) 3477.44,3283.58 cw(c3275.59,3283.58) 3275.59,3081.73 cw(c3275.59,3283.58) 3073.74,3283.58 ; 3073.74,6669.41 ccw(c3275.59,6669.41) 3275.59,6467.56 ccw(c3275.59,6669.41) 3440.42,6552.89 ccw(c3436.33,6555.78) 3441.22,6554.7 ccw(c3438.49,6558.89) 3442.62,6556.08 ccw(c3275.59,6669.41) 3477.44,6669.41 ccw(c3275.59,6669.41) 3275.59,6871.26 ccw(c3275.59,6669.41) 3073.74,6669.41 ; 6459.57,3283.58 ccw(c6661.42,3283.58) 6661.42,3081.73 ccw(c6661.42,3283.58) 6863.27,3283.58 ccw(c6661.42,3283.58) 6661.42,3485.43 ccw(c6661.42,3283.58) 6496.59,3400.1 ccw(c6500.67,3397.21) 6495.79,3398.29 ccw(c6498.52,3394.1) 6494.38,3396.91 ccw(c6661.42,3283.58) 6459.57,3283.58 ; 6459.57,6669.41 cw(c6661.42,6669.41) 6661.42,6871.26 cw(c6661.42,6669.41) 6863.27,6669.41 cw(c6661.42,6669.41) 6661.42,6467.56 cw(c6661.42,6669.41) 6496.59,6552.89 cw(c6500.67,6555.78) 6495.79,6554.7 cw(c6498.52,6558.89) 6494.38,6556.08 cw(c6661.42,6669.41) 6459.57,6669.41
  lines w10: 3538.13,3367.39 cw(c3275.59,3283.58) 3375.89,3540.27 4255,4410.49 ; 3538.13,6585.6 ccw(c3275.59,6669.41) 3375.89,6412.72 4255,5542.5 ; 3540,3367.99 4383.88,4189.09 ; 3540,6585 4383.88,5763.9 5554.8,5763.9 5550.75,5763.9 ; 4255.96,4411.44 4255.96,5542.5 ; 4384.39,4189.09 5553.04,4189.09 ; 5553.13,4189.09 6397.01,3367.99 ; 5553.13,5763.9 6397.01,6585 ; 5677.17,5540 5677.17,4412.83 5680,4410 ; 5682.01,4410.49 6561.12,3540.27 cw(c6661.42,3283.58) 6398.88,3367.39 ; 5682.01,5542.5 6561.12,6412.72 ccw(c6661.42,6669.41) 6398.88,6585.6

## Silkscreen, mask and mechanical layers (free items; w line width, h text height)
Top Silkscreen Layer:
  text "MIGO TECH" at 5095,5610 h98.43
Mechanical Layer:
  lines w0.1: 3073.74,3283.58 cw(c3275.59,3283.58) 3275.59,3485.43 cw(c3275.59,3283.58) 3440.42,3400.1 cw(c3436.33,3397.21) 3441.22,3398.29 cw(c3438.49,3394.1) 3442.62,3396.91 cw(c3275.59,3283.58) 3477.44,3283.58 cw(c3275.59,3283.58) 3275.59,3081.73 cw(c3275.59,3283.58) 3073.74,3283.58 ; 3073.74,6669.41 ccw(c3275.59,6669.41) 3275.59,6467.56 ccw(c3275.59,6669.41) 3440.42,6552.89 ccw(c3436.33,6555.78) 3441.22,6554.7 ccw(c3438.49,6558.89) 3442.62,6556.08 ccw(c3275.59,6669.41) 3477.44,6669.41 ccw(c3275.59,6669.41) 3275.59,6871.26 ccw(c3275.59,6669.41) 3073.74,6669.41 ; 6459.57,3283.58 ccw(c6661.42,3283.58) 6661.42,3081.73 ccw(c6661.42,3283.58) 6863.27,3283.58 ccw(c6661.42,3283.58) 6661.42,3485.43 ccw(c6661.42,3283.58) 6496.59,3400.1 ccw(c6500.67,3397.21) 6495.79,3398.29 ccw(c6498.52,3394.1) 6494.38,3396.91 ccw(c6661.42,3283.58) 6459.57,3283.58 ; 6459.57,6669.41 cw(c6661.42,6669.41) 6661.42,6871.26 cw(c6661.42,6669.41) 6863.27,6669.41 cw(c6661.42,6669.41) 6661.42,6467.56 cw(c6661.42,6669.41) 6496.59,6552.89 cw(c6500.67,6555.78) 6495.79,6554.7 cw(c6498.52,6558.89) 6494.38,6556.08 cw(c6661.42,6669.41) 6459.57,6669.41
